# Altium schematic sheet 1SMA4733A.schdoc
size 127 x 101 mm
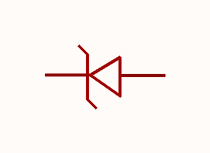
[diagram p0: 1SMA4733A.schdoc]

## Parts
D?  1sma4733a_c173487  [SMA_L4.4-W2.6-LS5.0-RD]  (value not drawn)

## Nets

Not connected (* = marked no-connect by the designer): D? 1(K) 2(A)

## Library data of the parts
D? = 1sma4733a_c173487: 二极管配置:1个独立式;稳压值(标称值):5.1V;稳压值(范围):4.84V~5.36V;耗散功率(Pd):1W;; Manufacturer: MDD(辰达半导体); AddInBom: yes; ModelId: a2d22152f8d5421c8e96dbd56af7c345; ModelTransform: 204.724,98.425,0,0,0,0,0,0,0; Diode Configuration: 1个独立式; Zener Voltage(Nom): 5.1V; Reverse Leakage Current (Ir): 10uA; Pd - Power Dissipation: 1W; Impedance(Zzt): 7Ω; Operating Junction Temperature Range: -55℃~+150℃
